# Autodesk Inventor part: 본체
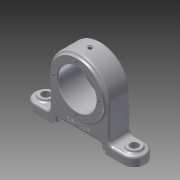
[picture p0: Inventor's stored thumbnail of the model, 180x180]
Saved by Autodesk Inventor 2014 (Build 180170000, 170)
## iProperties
Created: 2019-05
Part Number: 본체
Material: Aluminum 6061
Document SubType Name: Modeling
Designer: kh
Density: 2.71 g/cm^3
Appearance: Aluminum - Flat
Mass: 453.266 g
Surface Area: 315.114 cm^2
Volume: 167.257 cm^3
Author: kh
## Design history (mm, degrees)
sketch "Sketch1"
  geometry: L1 (-60, -15)-(60, -15); L2 (60, 15)-(-60, 15); L3 (0, 15)-(0, -15); A1 r 15 centre (60, 0) between (60, -15) and (60, 15); A2 r 15 centre (-60, 0) between (-60, 15) and (-60, -15); 2 further points
  constraints: 6 end point, 4 point on circle, 3 midpoint, 2 centre point, 1 coincident, 1 horizontal, 1 parallel, 1 tangent, 1 vertical
  dimensions: "d0" = 120 distance of L2.start L2.end; "d2" = 30 distance of L1.end L2.start; "d3" = 15 radius of A1; "d4" = 15 radius of A2; "d5" = 150 dimension on A1 A2 (derived)
extrude "Extrusion1" new body sketch "Sketch1" distance "d6" = 12; taper "d7" = 0 deg
sketch "Sketch2"
  geometry: C1 r 9 at (-60, 0); C2 r 9 at (60, 0); A1 r 15 centre (60, 0) between (60, -15) and (60, 15) reference; A2 r 15 centre (-60, 0) between (-60, 15) and (-60, -15) reference; 1 further point
  constraints: 2 centre point, 2 coincident
  dimensions: "d8" = 9 radius of C1; "d9" = 9 radius of C2
extrude "Extrusion2" join sketch "Sketch2" distance "d10" = 3; taper "d11" = 0 deg
sketch "Sketch4"
  geometry: L1 (-60, 0)-(60, 0) reference; L2 (-60, 12)-(60, 12) reference; L3 (40, 60)-(40, 12); L4 (-40, 60)-(-40, 12); L5 (-40, 12)-(40, 12); C1 r 36 at (0, 60); A1 r 40 centre (0, 60) between (40, 60) and (-40, 60); 2 further points
  constraints: 6 end point, 2 centre point, 2 perpendicular, 2 point on circle, 2 point on line, 2 tangent, 1 coincident, 1 collinear, 1 midpoint, 1 vertical alignment
  dimensions: "d12" = 40 radius of A1; "d13" = 60 distance from line of L1 A1.centre; "d86" = 36 radius of C1
extrude "Extrusion3" join sketch "Sketch4" stored distance "d14" = 30; taper "d15" = 0 deg
extrude "Extrusion4" join sketch "Sketch4" stored distance "d16" = 30; taper "d17" = 0 deg
sketch "Sketch10"
  geometry: C1 r 36 at (0, 60); 1 further point
  constraints: 1 centre point, 1 vertical alignment
  dimensions: "d91" = 36 radius of C1; "d92" = 60 distance of point (0, 0) C1.centre
extrude "Extrusion6" join sketch "Sketch10" stored distance "d93" = 36; taper "d94" = 0 deg
hole "Hole2" diameter "d29" = 11; stored, may be unused: countersink angle "d33" = 90 deg, drill point angle "d35" = 118 deg; dims "d27" = 10, "d28" = 10, "d30" = 6, "d31" = 4, "d32" = 2, "d34" = 8
hole "Hole3" diameter "d38" = 11; stored, may be unused: countersink angle "d42" = 90 deg, drill point angle "d44" = 118 deg; dims "d36" = 10, "d37" = 10, "d39" = 6, "d40" = 4, "d41" = 2, "d43" = 8
workplane "Work Plane1"
sketch "Sketch7"
  geometry: 4 further points
  constraints: 3 coincident
hole "Hole6" sketch "Sketch7" at (0, 0) diameter "d65" = 4.917; stored, may be unused: countersink angle "d69" = 90 deg, drill point angle "d71" = 118 deg; dims "d66" = 8, "d67" = 7, "d68" = 1, "d70" = 10
fillet "Fillet1" dims "d82" = 6
fillet "Fillet2" dims "d83" = 3
fillet "Fillet3" dims "d84" = 3
hole "Hole8" diameter "d97" = 52; stored, may be unused: countersink angle "d101" = 90 deg, drill point angle "d103" = 118 deg; dims "d95" = 10, "d96" = 10, "d98" = 2, "d99" = 19.05, "d100" = 4.775, "d102" = 8
sketch "Sketch11"
  geometry: L1 (0, 0)-(0, -31); C1 r 36 at (0, 0) reference; 2 further points
  constraints: 2 end point, 1 coincident, 1 vertical
  dimensions: "d104" = 31 distance of L1.start L1.end
hole "Hole9" sketch "Sketch11" at (0, -31) diameter "d105" = 3.242; stored, may be unused: countersink angle "d109" = 90 deg, drill point angle "d111" = 118 deg; dims "d106" = 6, "d107" = 19.05, "d108" = 4.775, "d110" = 8
pattern_circular "Circular Pattern2" dims angle "d113" = 360 deg
mirror "Mirror2"
sketch "Sketch12"
  geometry: L1 (0, 0)-(0, -26); C1 r 36 at (0, 0) reference; 2 further points
  constraints: 2 coincident, 2 end point, 1 vertical
  dimensions: "d115" = 26 distance of L1.start L1.end
hole "Hole10" sketch "Sketch12" at (0, -26) diameter "d116" = 3; stored, may be unused: countersink angle "d120" = 90 deg, drill point angle "d122" = 118 deg; dims "d117" = 6, "d118" = 19.05, "d119" = 4.775, "d121" = 8
fillet "Fillet5" dims "d123" = 3
chamfer "Chamfer2" distance "d124" = 1; stored, may be unused: second distance "d125" = 2, angle "d126" = 45 deg
sketch "Sketch14"
  geometry: L1 (120, 0)-(0, 0) reference; L2 (23, -47.671)-(23, -18) reference; L3 (96, 0)-(96, -4); L4 (96, -4)-(90, -4); L5 (90, -4)-(90, -10); L6 (90, -10)-(30, -10); L7 (30, -10)-(30, -4); L8 (30, -4)-(24, -4); L9 (24, -4)-(24, 0); L10 (96, 0)-(24, 0); 3 further points
  constraints: 16 end point, 4 perpendicular, 3 parallel, 2 equal length, 2 midpoint, 2 point on line, 1 coincident, 1 collinear
  dimensions: "d128" = 4 distance of L3.start L3.end; "d129" = 6 distance of L4.end L5.end; "d130" = 60 distance of L5.end L6.end; "d131" = 72 distance of L3.start L9.end
extrude "Extrusion7" cut sketch "Sketch14" stored distance "d132" = 36; taper "d133" = 0 deg
fillet "Fillet6" dims "d134" = 3
fillet "Fillet7" dims "d135" = 3
workplane "Work Plane3"
sketch "Sketch15"
  geometry: L1 (76.592, -10.402)-(43.408, -10.402); L2 (43.408, -10.402)-(43.408, -5.598); L3 (43.408, -5.598)-(76.592, -5.598); L4 (76.592, -5.598)-(76.592, -10.402); L5 (76.592, -10.402)-(43.408, -5.598); L6 (76.592, -5.598)-(43.408, -10.402); L7 (87, -1)-(33, -1) reference; 3 further points
  constraints: 4 end point, 2 midpoint, 1 vertical alignment, 2 other
  dimensions: "d137" = 7 distance from line of L7 point (60, -8)
emboss "Emboss1" sketch "Sketch15" dims "d0" = 120, "d2" = 30, "d3" = 15, "d4" = 15, "d5" = 150 (derived), "d12" = 40, "d13" = 60, "d86" = 36, "d138" = 0.5, "d139" = 0
sketch "Sketch16"
  geometry: 2 further points
  constraints: 1 coincident
hole "Hole11" sketch "Sketch16" at (0, 0) diameter "d140" = 3; stored, may be unused: countersink angle "d144" = 90 deg, drill point angle "d146" = 0 deg; dims "d141" = 6, "d142" = 4, "d143" = 2, "d145" = 20
body "Solid1"
other parameters: "d136" = 44
